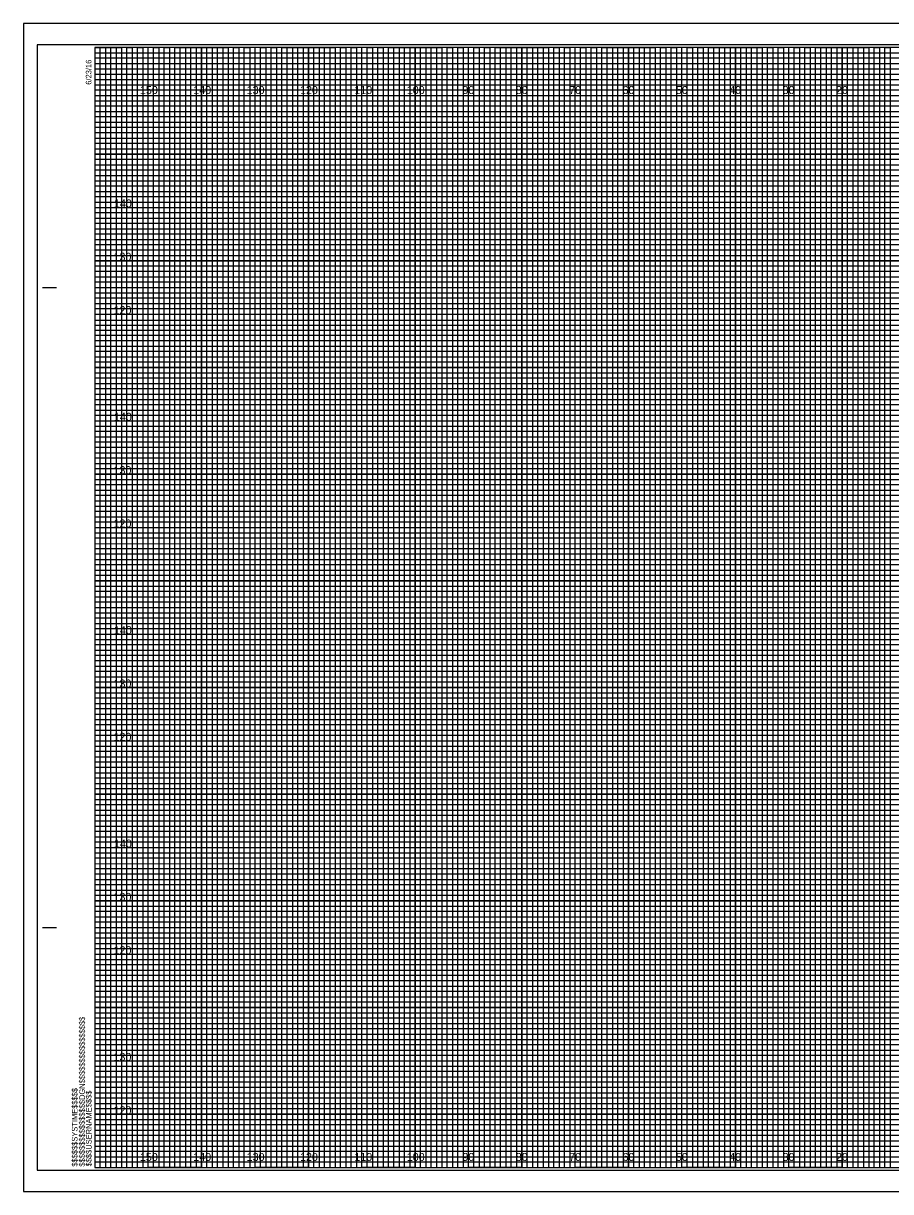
# Model space of a CAD drawing. Extents: x -13 to 323, y -5 to 654.
# Drawn here: x -13.4 to 149.1, y -4.5 to 214.5 of the extents above; entities that cross this region are included whole.
import ezdxf

# ---------------------------------------------------------------- set-up
doc = ezdxf.new("R2010")
doc.units = 0
for name, color, linetype in [('Prop XS Elevation Labels', 7, 'Continuous'), ('Prop XS Offset Labels', 7, 'Continuous'), ('Sheet Cross Section CELL', 7, 'Continuous'), ('Sheet Cross Section Grid Major CELL', 7, 'Continuous'), ('Sheet Cross Section Grid Middle CELL', 7, 'Continuous'), ('Sheet Cross Section Grid Minor 1 CELL', 7, 'Continuous'), ('Sheet Cross Section Grid Minor 2 CELL', 7, 'Continuous'), ('Sheet Cutting Line CELL', 7, 'Continuous'), ('Sheet DOT Grid CELL', 7, 'Continuous'), ('Sheet Plot Border Inside CELL', 7, 'Continuous'), ('Sheet Plot Border Outside CELL', 7, 'Continuous')]:
    doc.layers.add(name, color=color, linetype=linetype)

msp = doc.modelspace()

# ---------------------------------------------------------------- linework, layer by layer
at = {"layer": 'Sheet Cross Section CELL'}
for p, q in [((-9.8, 165), (-7.3, 165)), ((-9.7, 165), (-7.2, 165)), ((-9.8, 45), (-7.3, 45)), ((-9.7, 45), (-7.2, 45)), ((0, 0), (0, 0)), ((0, 0), (0, 0)), ((0, 0), (0, 0)), ((0, 0), (0, 0)), ((0, 0), (0, 0)), ((0, 0), (0, 0)), ((0, 0), (0, 0))]:
    msp.add_line(p, q, dxfattribs=at)
msp.add_lwpolyline([(320, 210), (0, 210), (0, 0), (320, 0)], close=True, dxfattribs=at)
at = {"layer": 'Sheet Cross Section Grid Major CELL'}
for p, q in [((10, 210), (0, 210)), ((10, 0), (10, 210)), ((30, 210), (20, 210)), ((20, 210), (20, 0)), ((30, 0), (30, 210)), ((50, 210), (40, 210)), ((40, 210), (40, 0)), ((50, 0), (50, 210)), ((70, 210), (60, 210)), ((60, 210), (60, 0)), ((70, 0), (70, 210)), ((90, 210), (80, 210)), ((80, 210), (80, 0)), ((90, 0), (90, 210)), ((110, 210), (100, 210)), ((100, 210), (100, 0)), ((110, 0), (110, 210)), ((130, 210), (120, 210)), ((120, 210), (120, 0)), ((130, 0), (130, 210)), ((150, 210), (140, 210)), ((140, 210), (140, 0)), ((20, 0), (10, 0)), ((40, 0), (30, 0)), ((60, 0), (50, 0)), ((80, 0), (70, 0)), ((100, 0), (90, 0)), ((120, 0), (110, 0)), ((140, 0), (130, 0))]:
    msp.add_line(p, q, dxfattribs=at)
for points in [[(0, 200), (320, 200), (320, 190), (0, 190)], [(0, 180), (320, 180), (320, 170), (0, 170)], [(0, 160), (320, 160), (320, 150), (0, 150)], [(0, 140), (320, 140), (320, 130), (0, 130)], [(0, 120), (320, 120), (320, 110), (0, 110)], [(0, 100), (320, 100), (320, 90), (0, 90)], [(0, 80), (320, 80), (320, 70), (0, 70)], [(0, 60), (320, 60), (320, 50), (0, 50)], [(0, 40), (320, 40), (320, 30), (0, 30)], [(0, 20), (320, 20), (320, 10), (0, 10)]]:
    msp.add_lwpolyline(points, dxfattribs=at)
at = {"layer": 'Sheet Cross Section Grid Middle CELL'}
for points in [[(0, 210), (5, 210), (5, 0), (15, 0), (15, 210), (25, 210), (25, 0), (35, 0), (35, 210), (45, 210), (45, 0), (55, 0), (55, 210), (65, 210), (65, 0), (75, 0), (75, 210), (85, 210), (85, 0), (95, 0), (95, 210), (105, 210), (105, 0), (115, 0), (115, 210), (125, 210), (125, 0), (135, 0), (135, 210), (145, 210), (145, 0), (155, 0)], [(0, 205), (275, 205)], [(0, 185), (320, 185), (320, 195), (0, 195)], [(0, 165), (320, 165), (320, 175), (0, 175)], [(0, 145), (320, 145), (320, 155), (0, 155)], [(0, 125), (320, 125), (320, 135), (0, 135)], [(0, 105), (320, 105), (320, 115), (0, 115)], [(0, 85), (320, 85), (320, 95), (0, 95)], [(0, 65), (320, 65), (320, 75), (0, 75)], [(0, 45), (320, 45), (320, 55), (0, 55)], [(0, 25), (320, 25), (320, 35), (0, 35)], [(0, 5), (320, 5), (320, 15), (0, 15)]]:
    msp.add_lwpolyline(points, dxfattribs=at)
at = {"layer": 'Sheet Cross Section Grid Minor 1 CELL'}
for p, q in [((0, 209), (260, 209)), ((260, 207.98), (0, 207.98)), ((0, 207.98), (0, 207)), ((0, 207), (260, 207)), ((260, 205.89), (0, 205.89)), ((0, 205.89), (0, 204)), ((0, 204), (320, 204))]:
    msp.add_line(p, q, dxfattribs=at)
for points in [[(0, 203), (270, 203), (320, 203), (320, 202), (0, 202)], [(0, 201), (320, 201), (320, 199), (0, 199)], [(0, 198), (320, 198), (320, 197), (0, 196.98)], [(0, 196), (320, 196), (320, 194), (0, 194)], [(0, 193), (320, 193), (320, 192), (0, 192)], [(0, 191), (320, 191), (320, 189), (0, 189)], [(0, 188), (320, 188), (320, 187), (0, 187)], [(0, 186), (320, 186), (320, 184), (0, 184)], [(0, 183), (320, 183), (320, 182), (0, 182)], [(0, 181), (320, 181), (320, 179), (0, 179)], [(0, 178), (320, 178), (320, 177), (0, 177)], [(0, 176), (320, 176), (320, 173.95), (320, 173), (320, 172), (0, 172)], [(0, 174), (320, 174), (320, 173), (0, 173)], [(0, 171), (320, 171), (320, 169), (0, 169.03)], [(0, 169.03), (320, 169), (320, 168), (0, 168)], [(0, 167), (320, 167), (320, 166), (0, 166)], [(0, 164), (320, 164), (320, 163), (0, 163)], [(0, 162), (320, 162), (320, 161), (0, 161)], [(-0.07, 158.89), (320, 158.89), (320, 157.88), (-0.07, 157.88)], [(0, 157), (320, 157), (320, 156), (0, 156)], [(0, 154), (320, 154), (320, 153), (0, 153)], [(0, 152), (320, 152), (320, 151), (0, 151)], [(0, 149), (320, 149), (320, 148), (0, 148)], [(0, 147), (320, 147), (320, 146), (0, 146)], [(0, 144), (320, 144), (320, 143), (0, 143)], [(0, 142), (320, 142), (320, 141), (0, 141)], [(0, 139), (320, 139), (319.99, 137.98), (0, 138)], [(0, 137), (320, 137), (320, 136), (0, 136)], [(0, 134), (320, 134), (320, 133), (0, 133)], [(0, 132), (320, 132), (320, 131), (0, 131)], [(0, 129), (320, 129), (320, 128), (0, 128)], [(0, 127), (320, 127), (320, 126), (0, 126)], [(0, 124), (320, 124), (320, 123), (0, 123)], [(0, 122), (320, 122), (320, 121), (0, 121)], [(0, 119), (320, 119), (320, 118), (0, 118)], [(0, 116.99), (320.07, 116.91), (320, 116), (0, 116)], [(0, 114), (320, 114), (320, 113), (0, 113)], [(0, 112), (320, 112), (320, 111), (0, 111)], [(0, 109), (320, 109), (320, 108), (0, 108)], [(0, 107), (320, 107), (320, 106), (0, 106)], [(0, 104), (320, 104), (320, 103), (0, 103)], [(0, 102), (320, 102), (320, 101), (0, 101)], [(0, 99), (320, 99), (320, 98), (0, 98)], [(0, 97), (320, 97), (320, 96), (0, 96)], [(0, 94), (320, 94), (320, 93), (0, 93)], [(0, 92), (320, 92), (320, 91), (0, 91)], [(0, 89), (320, 89), (320, 88), (0, 88)], [(0, 87), (320, 87), (320, 86), (0, 86)], [(0, 84), (320, 84), (320, 83), (0, 83)], [(0, 82), (320, 82), (320, 81), (0, 81)], [(0, 79), (320, 79), (319.99, 77.98), (0, 78)], [(0, 77), (320, 77), (320, 76), (0, 76)], [(0, 74), (320, 74), (320, 73), (0, 73)], [(0, 72), (320, 72), (320, 71), (0, 71)], [(0, 69), (320, 69), (320, 68), (0, 68)], [(0, 67), (320, 67), (320, 66), (0, 66)], [(0, 64), (320, 64), (320, 63), (0, 63)], [(0, 62), (320, 62), (320, 61), (0, 61)], [(0, 59), (320, 59), (320, 58), (0, 58)], [(0, 56.99), (320.07, 56.91), (320, 56), (0, 56)], [(0, 54), (320, 54), (320, 53), (0, 53)], [(0, 52), (320, 52), (320, 51), (0, 51)], [(0, 49), (320, 49), (320, 48), (0, 48)], [(0, 47), (320, 47), (320, 46), (0, 46)], [(0, 44), (320, 44), (320, 43), (0, 43)], [(0, 42), (320, 42), (320, 41), (0, 41)], [(0, 39), (320, 39), (320, 38), (0, 38)], [(0, 37), (320, 37), (320, 36), (0, 36)], [(0, 34), (320, 34), (320, 33), (0, 33)], [(0, 32), (320, 32), (320, 31), (0, 31)], [(0, 29), (320, 29), (320, 28), (0, 28)], [(0, 27), (320, 27), (320, 26), (0, 26)], [(0, 24), (320, 24), (320, 23), (0, 23)], [(0, 22), (320, 22), (320, 21), (0, 21)], [(0, 19), (320, 19), (320, 18), (0, 18)], [(0, 17), (320, 17), (320, 16), (0, 16)], [(0, 14), (320, 14), (320, 13), (0, 13)], [(0, 12), (320, 12), (320, 11), (0, 11)], [(0, 9), (320, 9), (320, 8), (0, 8)], [(0, 7), (320, 7), (320, 6), (0, 6)], [(0, 4), (320, 4), (320, 3), (0, 3)], [(0, 2), (320, 2), (320, 1), (0, 1)]]:
    msp.add_lwpolyline(points, dxfattribs=at)
at = {"layer": 'Sheet Cross Section Grid Minor 2 CELL'}
for points in [[(0, 0), (1, 0), (1, 210), (2, 210), (2, 0)], [(2, 0), (3, 0), (3, 210), (4, 210), (4, 0)], [(5, 0), (6, 0), (6, 210), (7, 210), (7, 0)], [(7, 0), (8, 0), (8, 210), (9, 210), (9, 0)], [(10, 0), (11, 0), (11, 210), (12, 210), (12, 0)], [(12, 0), (13, 0), (13, 210), (14, 210), (14, 0)], [(15, 0), (16, 0), (16, 210), (17, 210), (17, 0)], [(17, 0), (18, 0), (18, 210), (19, 210), (19, 0)], [(20, 0), (21, 0), (21, 210), (22, 210), (22, 0)], [(22, 0), (23, 0), (23, 210), (24, 210), (24, 0)], [(25, 0), (26, 0), (26, 210), (27, 210), (27, 0)], [(27, 0), (28, 0), (28, 210), (29, 210), (29, 0)], [(30, 0), (31, 0), (31, 210), (32, 210), (32, 0)], [(32, 0), (33, 0), (33, 210), (34, 210), (34, 0)], [(35, 0), (36, 0), (36, 210), (37, 210), (37, 0)], [(37, 0), (38, 0), (38, 210), (39, 210), (39, 0)], [(40, 0), (41, 0), (41, 210), (42, 210), (42, 0)], [(42, 0), (43, 0), (43, 210), (44, 210), (44, 0)], [(45, 0), (46, 0), (46, 210), (47, 210), (47, 0)], [(47, 0), (48, 0), (48, 210), (49, 210), (49, 0)], [(50, 0), (51, 0), (51, 210), (52, 210), (52, 0)], [(52, 0), (53, 0), (53, 210), (54, 210), (54, 0)], [(55, 0), (56, 0), (56, 210), (57, 210), (57, 0)], [(57, 0), (58, 0), (58, 210), (59, 210), (59, 0)], [(60, 0), (61, 0), (61, 210), (62, 210), (62, 0)], [(62, 0), (63, 0), (63, 210), (64, 210), (64, 0)], [(65, 0), (66, 0), (66, 210), (67, 210), (67, 0)], [(67, 0), (68, 0), (68, 210), (69, 210), (69, 0)], [(70, 0), (71, 0), (71, 210), (72, 210), (72, 0)], [(72, 0), (73, 0), (73, 210), (74, 210), (74, 0)], [(75, 0), (76, 0), (76, 210), (77, 210), (77, 0)], [(77, 0), (78, 0), (78, 210), (79, 210), (79, 0)], [(80, 0), (81, 0), (81, 210), (82, 210), (82, 0)], [(82, 0), (83, 0), (83, 210), (84, 210), (84, 0)], [(85, 0), (86, 0), (86, 210), (87, 210), (87, 0)], [(87, 0), (88, 0), (88, 210), (89, 210), (89, 0)], [(90, 0), (91, 0), (91, 210), (92, 210), (92, 0)], [(92, 0), (93, 0), (93, 210), (94, 210), (94, 0)], [(95, 0), (96, 0), (96, 210), (97, 210), (97, 0)], [(97, 0), (98, 0), (98, 210), (99, 210), (99, 0)], [(100, 0), (101, 0), (101, 210), (102, 210), (102, 0)], [(102, 0), (103, 0), (103, 210), (104, 210), (104, 0)], [(105, 0), (106, 0), (106, 210), (107, 210), (107, 0)], [(107, 0), (108, 0), (108, 210), (109, 210), (109, 0)], [(110, 0), (111, 0), (111, 210), (112, 210), (112, 0)], [(112, 0), (113, 0), (113, 210), (114, 210), (114, 0)], [(115, 0), (116, 0), (116, 210), (117, 210), (117, 0)], [(117, 0), (118, 0), (118, 210), (119, 210), (119, 0)], [(120, 0), (121, 0), (121, 210), (122, 210), (122, 0)], [(122, 0), (123, 0), (123, 210), (124, 210), (124, 0)], [(125, 0), (126, 0), (126, 210), (127, 210), (127, 0)], [(127, 0), (128, 0), (128, 210), (129, 210), (129, 0)], [(130, 0), (131, 0), (131, 210), (132, 210), (132, 0)], [(132, 0), (133, 0), (133, 210), (134, 210), (134, 0)], [(135, 0), (136, 0), (136, 210), (137, 210), (137, 0)], [(137, 0), (138, 0), (138, 210), (139, 210), (139, 0)], [(140, 0), (141, 0), (141, 210), (142, 210), (142, 0)], [(142, 0), (143, 0), (143, 210), (144, 210), (144, 0)], [(145, 0), (146, 0), (146, 210), (147, 210), (147, 0)], [(147, 0), (148, 0), (148, 210), (149, 210), (149, 0)]]:
    msp.add_lwpolyline(points, dxfattribs=at)
at = {"layer": 'Sheet Cutting Line CELL'}
for p, q in [((323.3, 214.5), (-13.4, 214.5)), ((-13.4, 214.5), (-13.4, -4.5)), ((-13.4, -4.5), (323.3, -4.5))]:
    msp.add_line(p, q, dxfattribs=at)
at = {"layer": 'Sheet DOT Grid CELL'}
for p, q in [((10, 0), (10, 210)), ((20, 0), (20, 210)), ((30, 0), (30, 210)), ((40, 0), (40, 210)), ((50, 0), (50, 210)), ((60, 0), (60, 210)), ((70, 0), (70, 210)), ((80, 0), (80, 210)), ((90, 0), (90, 210)), ((100, 0), (100, 210)), ((110, 0), (110, 210)), ((120, 0), (120, 210)), ((130, 0), (130, 210)), ((140, 0), (140, 210)), ((0, 200), (320, 200)), ((0, 190), (320, 190)), ((0, 180), (320, 180)), ((0, 170), (320, 170)), ((0, 160), (320, 160)), ((0, 150), (320, 150)), ((0, 140), (320, 140)), ((0, 130), (320, 130)), ((0, 120), (320, 120)), ((0, 110), (320, 110)), ((0, 100), (320, 100)), ((0, 90), (320, 90)), ((0, 80), (320, 80)), ((0, 70), (320, 70)), ((0, 60), (320, 60)), ((0, 50), (320, 50)), ((0, 40), (320, 40)), ((0, 30), (320, 30)), ((0, 20), (320, 20)), ((0, 10), (320, 10))]:
    msp.add_line(p, q, dxfattribs=at)
at = {"layer": 'Sheet Plot Border Inside CELL'}
msp.add_lwpolyline([(-10.8, -0.5), (322.4, -0.5), (322.4, 210.5), (-10.8, 210.5)], close=True, dxfattribs=at)
at = {"layer": 'Sheet Plot Border Outside CELL'}
msp.add_lwpolyline([(-13.4, -4.5), (323.3, -4.5), (323.3, 214.5), (-13.4, 214.5)], close=True, dxfattribs=at)

# ---------------------------------------------------------------- texts
at = {"layer": 'Prop XS Elevation Labels'}
for s, p in [('140', (3.57, 180)), ('130', (3.49, 170)), ('120', (3.5, 160)), ('140', (3.57, 140)), ('130', (3.49, 130)), ('120', (3.5, 120)), ('140', (3.57, 100)), ('130', (3.49, 90)), ('120', (3.5, 80)), ('140', (3.57, 60)), ('130', (3.49, 50)), ('120', (3.5, 40)), ('130', (3.49, 20)), ('120', (3.5, 10))]:
    msp.add_text(s, height=1.5, dxfattribs=at).set_placement(p)
at = {"layer": 'Prop XS Offset Labels'}
for s, p in [('150', (8.44, 201.25)), ('140', (18.44, 201.25)), ('130', (28.44, 201.25)), ('120', (38.44, 201.25)), ('110', (48.62, 201.25)), ('100', (58.44, 201.25)), ('90', (68.86, 201.25)), ('80', (78.86, 201.25)), ('70', (88.86, 201.25)), ('60', (98.86, 201.25)), ('50', (108.86, 201.25)), ('40', (118.86, 201.25)), ('30', (128.86, 201.25)), ('20', (138.86, 201.25)), ('150', (8.44, 1.25)), ('140', (18.44, 1.25)), ('130', (28.44, 1.25)), ('120', (38.44, 1.25)), ('110', (48.62, 1.25)), ('100', (58.44, 1.25)), ('90', (68.86, 1.25)), ('80', (78.86, 1.25)), ('70', (88.86, 1.25)), ('60', (98.86, 1.25)), ('50', (108.86, 1.25)), ('40', (118.86, 1.25)), ('30', (128.86, 1.25)), ('20', (138.86, 1.25))]:
    msp.add_text(s, height=1.5, dxfattribs=at).set_placement(p)
at = {"layer": 'Sheet Cross Section CELL'}
for s, p in [('6/23/16', (-0.65, 203)), ('$$$$$$$$$$$$$$$$DGN$$$$$$$$$$$$$$$$', (-1.88, 0.18)), ('$$$$$$SYSTIME$$$$$', (-3.26, 0.18)), ('$$$$USERNAME$$$$', (-0.62, 0.23))]:
    msp.add_text(s, height=1.05, rotation=90, dxfattribs=at).set_placement(p)

doc.saveas('drawing.dxf')
